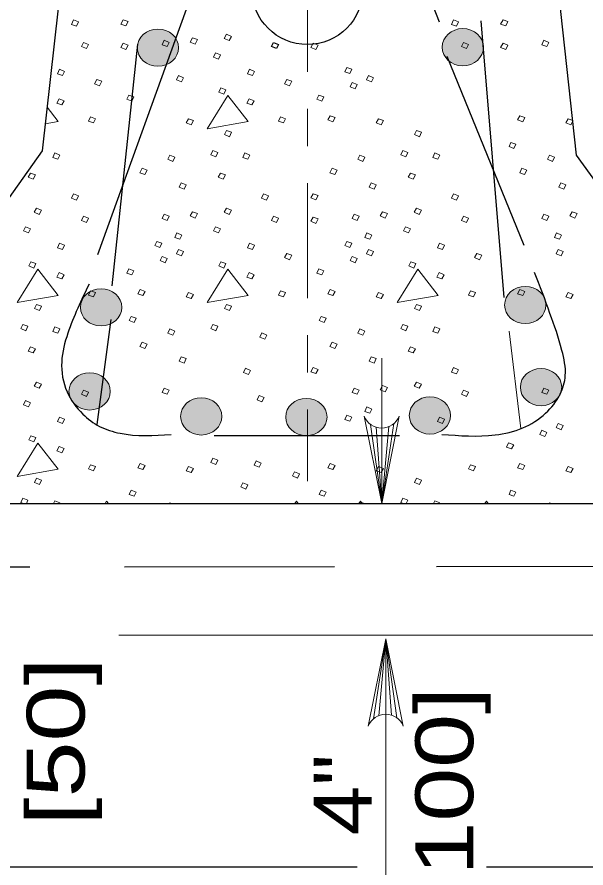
# Model space of a CAD drawing. Extents: x 1083.1 to 1123, y 697.4 to 741.4.
# Drawn here: x 1092.52 to 1094.054, y 703.761 to 706.055 of the extents above; entities that cross this region are included whole.
import ezdxf
from ezdxf.enums import TextEntityAlignment as Align

# ---------------------------------------------------------------- set-up
doc = ezdxf.new("R2010")
doc.units = 0
doc.header["$LTSCALE"] = 0.062
doc.linetypes.add('DOT_DASHED', pattern=[7.7, 5, -1.2, 0.3, -1.2])
doc.layers.add('1', color=7, linetype='Continuous', lineweight=13)

msp = doc.modelspace()

# ---------------------------------------------------------------- hatches: boundary and pattern name
at = {"layer": '1'}
h = msp.add_hatch(color=256, dxfattribs=at)
edge = h.paths.add_edge_path()
edge.add_ellipse((1092.89979, 705.97227), major_axis=(0.05572, 0), ratio=0.8999053, start_angle=0, end_angle=360)
h = msp.add_hatch(color=256, dxfattribs=at)
edge = h.paths.add_edge_path()
edge.add_ellipse((1093.72164, 705.97356), major_axis=(0.05572, 0), ratio=0.8999053, start_angle=0, end_angle=360)
h = msp.add_hatch(color=256, dxfattribs=at)
edge = h.paths.add_edge_path()
edge.add_ellipse((1093.89001, 705.27866), major_axis=(0.05572, 0), ratio=0.8999053, start_angle=0, end_angle=360)
h = msp.add_hatch(color=256, dxfattribs=at)
edge = h.paths.add_edge_path()
edge.add_ellipse((1092.74659, 705.27236), major_axis=(0.05572, 0), ratio=0.8999053, start_angle=0, end_angle=360)
h = msp.add_hatch(color=256, dxfattribs=at)
edge = h.paths.add_edge_path()
edge.add_ellipse((1093.93249, 705.05724), major_axis=(0.05572, 0), ratio=0.8999053, start_angle=0, end_angle=360)
h = msp.add_hatch(color=256, dxfattribs=at)
edge = h.paths.add_edge_path()
edge.add_ellipse((1092.7157, 705.04577), major_axis=(0.05572, 0), ratio=0.8999053, start_angle=0, end_angle=360)
h = msp.add_hatch(color=256, dxfattribs=at)
edge = h.paths.add_edge_path()
edge.add_ellipse((1093.63301, 704.98095), major_axis=(0.05572, 0), ratio=0.8999053, start_angle=0, end_angle=360)
h = msp.add_hatch(color=256, dxfattribs=at)
edge = h.paths.add_edge_path()
edge.add_ellipse((1093.01662, 704.97837), major_axis=(0.05572, 0), ratio=0.8999053, start_angle=0, end_angle=360)
h = msp.add_hatch(color=256, dxfattribs=at)
edge = h.paths.add_edge_path()
edge.add_ellipse((1093.29994, 704.97667), major_axis=(0.05572, 0), ratio=0.8999053, start_angle=0, end_angle=360)

# ---------------------------------------------------------------- linework, layer by layer
at = {"layer": '1', "linetype": 'DOT_DASHED'}
msp.add_line((1093.30267, 707.43708), (1093.30267, 704.80367), dxfattribs=at)
at = {"layer": '1', "lineweight": 25}
for p, q in [((1093.16208, 706.59233), (1092.73708, 705.41425)), ((1093.65925, 706.04117), (1093.43958, 706.5975)), ((1093.83275, 705.299), (1093.77133, 706.04458)), ((1092.84492, 705.98158), (1092.77592, 705.33008)), ((1093.88683, 705.439), (1093.67975, 705.94892)), ((1092.77292, 705.23925), (1092.735, 704.95617)), ((1093.05133, 704.92658), (1093.55092, 704.92658)), ((1092.1595, 704.74317), (1094.45958, 704.74317)), ((1092.55433, 704.57217), (1092.09758, 704.57167)), ((1093.37617, 704.573), (1092.80958, 704.57242)), ((1094.23692, 704.57392), (1093.65075, 704.57333)), ((1092.13858, 703.76442), (1093.4365, 703.76442)), ((1093.78567, 703.76442), (1094.45983, 703.76442))]:
    msp.add_line(p, q, dxfattribs=at)
at = {"layer": '1'}
for p, q in [((1094.006, 705.78067), (1094.01808, 705.77625)), ((1093.84683, 705.20783), (1093.87842, 704.94542)), ((1093.50292, 705.13492), (1093.50292, 704.74317)), ((1093.47308, 704.95642), (1093.50292, 704.74317)), ((1093.48783, 704.94925), (1093.50292, 704.74317)), ((1093.53592, 704.959), (1093.50292, 704.74317)), ((1093.52208, 704.95083), (1093.50292, 704.74317)), ((1093.50292, 704.947), (1093.50292, 704.74317)), ((1092.61867, 704.74317), (1092.62217, 704.75108)), ((1092.76133, 704.7495), (1092.75742, 704.74317)), ((1092.76633, 704.74317), (1092.76133, 704.7495)), ((1092.93092, 704.74317), (1092.932, 704.74542)), ((1092.932, 704.74542), (1092.93733, 704.74317)), ((1093.27325, 704.7495), (1093.26925, 704.74317)), ((1093.27817, 704.74317), (1093.27325, 704.7495)), ((1093.44575, 704.7495), (1093.44175, 704.74317)), ((1093.44275, 704.74317), (1093.44383, 704.74542)), ((1093.44383, 704.74542), (1093.44925, 704.74317)), ((1093.45067, 704.74317), (1093.44575, 704.7495)), ((1093.44983, 704.74317), (1093.45092, 704.74542)), ((1093.45092, 704.74542), (1093.45633, 704.74317)), ((1093.64242, 704.74317), (1093.64592, 704.75108)), ((1093.78508, 704.7495), (1093.78117, 704.74317)), ((1093.79, 704.74317), (1093.78508, 704.7495)), ((1093.95458, 704.74317), (1093.95567, 704.74542)), ((1093.95567, 704.74542), (1093.96108, 704.74317)), ((1092.79442, 704.3885), (1094.97683, 704.3885)), ((1093.481, 704.16333), (1093.514, 704.37917)), ((1093.49483, 704.1715), (1093.514, 704.37917)), ((1093.514, 704.37917), (1093.514, 703.5205)), ((1093.514, 704.17533), (1093.514, 704.37917)), ((1093.52908, 704.17308), (1093.514, 704.37917)), ((1093.54383, 704.16592), (1093.514, 704.37917))]:
    msp.add_line(p, q, dxfattribs=at)
at = {"layer": '1', "lineweight": 25}
for points in [[(1092.759, 707.22517), (1092.58783, 705.69442), (1092.046, 704.92958)], [(1094.57242, 704.93058), (1094.02833, 705.68267), (1093.86025, 707.22475)]]:
    msp.add_lwpolyline(points, dxfattribs=at)
at = {"layer": '1'}
for points in [[(1092.67242, 706.04733), (1092.68592, 706.04167), (1092.68058, 706.03033), (1092.66708, 706.03517)], [(1092.80625, 706.04733), (1092.81975, 706.04242), (1092.81342, 706.03117), (1092.8, 706.036)], [(1093.69617, 706.04733), (1093.70967, 706.04167), (1093.70425, 706.03033), (1093.69075, 706.03517)], [(1093.83, 706.04733), (1093.84342, 706.04242), (1093.83717, 706.03117), (1093.82367, 706.036)], [(1092.99308, 705.99883), (1093.0065, 705.994), (1093.00025, 705.98183), (1092.98675, 705.9875)], [(1093.08467, 706.0085), (1093.09808, 706.00283), (1093.09183, 705.9915), (1093.07833, 705.99717)], [(1092.69942, 705.98667), (1092.71283, 705.981), (1092.7075, 705.96975), (1092.694, 705.97542)], [(1092.80625, 705.98425), (1092.81975, 705.97942), (1092.81342, 705.96733), (1092.8, 705.97292)], [(1092.91675, 705.99233), (1092.93017, 705.98667), (1092.92483, 705.97542), (1092.91133, 705.98025)], [(1093.31808, 705.98425), (1093.33158, 705.97942), (1093.32533, 705.96733), (1093.31183, 705.97292)], [(1093.72308, 705.98667), (1093.73658, 705.981), (1093.73125, 705.96975), (1093.71775, 705.97542)], [(1093.83, 705.98425), (1093.84342, 705.97942), (1093.83717, 705.96733), (1093.82367, 705.97292)], [(1093.94042, 705.99233), (1093.95392, 705.98667), (1093.9485, 705.97542), (1093.93508, 705.98025)], [(1093.055, 705.95842), (1093.0685, 705.95275), (1093.06308, 705.94142), (1093.04958, 705.94708)], [(1092.63475, 705.914), (1092.64825, 705.90833), (1092.64283, 705.897), (1092.62933, 705.90183)], [(1093.14658, 705.914), (1093.16008, 705.90833), (1093.15467, 705.897), (1093.14125, 705.90183)], [(1093.40883, 705.91883), (1093.42233, 705.914), (1093.41692, 705.90267), (1093.40342, 705.9075)], [(1092.73533, 705.8865), (1092.74875, 705.88167), (1092.7425, 705.8695), (1092.729, 705.87517)], [(1092.95533, 705.897), (1092.96883, 705.89133), (1092.96342, 705.88), (1092.94992, 705.88567)], [(1093.24717, 705.8865), (1093.26067, 705.88167), (1093.25433, 705.8695), (1093.24092, 705.87517)], [(1093.46717, 705.897), (1093.48067, 705.89133), (1093.47525, 705.88), (1093.46183, 705.88567)], [(1093.06933, 705.86383), (1093.08283, 705.859), (1093.0775, 705.84692), (1093.064, 705.85258)], [(1093.42317, 705.87842), (1093.43667, 705.87275), (1093.43125, 705.86142), (1093.41783, 705.86708)], [(1092.63383, 705.83475), (1092.64733, 705.82908), (1092.641, 705.81783), (1092.62758, 705.82267)], [(1092.8215, 705.8445), (1092.835, 705.83958), (1092.82958, 705.82833), (1092.81617, 705.83317)], [(1093.08825, 705.84367), (1093.03258, 705.75392), (1093.143, 705.77333)], [(1093.14567, 705.83475), (1093.15917, 705.82908), (1093.15292, 705.81783), (1093.13942, 705.82267)], [(1093.33342, 705.8445), (1093.34683, 705.83958), (1093.3415, 705.82833), (1093.328, 705.83317)], [(1093.36392, 705.78867), (1093.37742, 705.78383), (1093.37108, 705.77258), (1093.35767, 705.77742)], [(1093.87575, 705.78867), (1093.88925, 705.78383), (1093.883, 705.77258), (1093.8695, 705.77742)], [(1092.71825, 705.7855), (1092.73175, 705.78067), (1092.72633, 705.76933), (1092.71283, 705.77417)], [(1092.98225, 705.78067), (1092.99575, 705.77575), (1092.98942, 705.7645), (1092.976, 705.76933)], [(1093.23008, 705.7855), (1093.24358, 705.78067), (1093.23817, 705.76933), (1093.22475, 705.77417)], [(1093.49417, 705.78067), (1093.50758, 705.77575), (1093.50133, 705.7645), (1093.48783, 705.76933)], [(1093.08467, 705.74908), (1093.09808, 705.74425), (1093.09275, 705.73217), (1093.07925, 705.73783)], [(1093.5965, 705.74908), (1093.61, 705.74425), (1093.60458, 705.73217), (1093.59108, 705.73783)], [(1093.8515, 705.71675), (1093.865, 705.71192), (1093.85958, 705.70067), (1093.84617, 705.7055)], [(1092.62217, 705.6885), (1092.63567, 705.68283), (1092.63025, 705.6715), (1092.61675, 705.67633)], [(1092.932, 705.68283), (1092.94542, 705.67717), (1092.94008, 705.66583), (1092.92658, 705.6715)], [(1093.04783, 705.695), (1093.06133, 705.69008), (1093.05592, 705.678), (1093.04242, 705.68367)], [(1093.134, 705.6885), (1093.1475, 705.68283), (1093.14208, 705.6715), (1093.12867, 705.67633)], [(1093.44383, 705.68283), (1093.45733, 705.67717), (1093.45192, 705.66583), (1093.43842, 705.6715)], [(1093.55967, 705.695), (1093.57317, 705.69008), (1093.56775, 705.678), (1093.55433, 705.68367)], [(1093.64592, 705.6885), (1093.65933, 705.68283), (1093.654, 705.6715), (1093.6405, 705.67633)], [(1093.95567, 705.68283), (1093.96917, 705.67717), (1093.96375, 705.66583), (1093.95033, 705.6715)], [(1092.55658, 705.63433), (1092.57008, 705.6295), (1092.56383, 705.61817), (1092.55033, 705.623)], [(1092.85742, 705.64725), (1092.87092, 705.64167), (1092.86467, 705.63033), (1092.85117, 705.63517)], [(1093.0685, 705.63433), (1093.08192, 705.6295), (1093.07567, 705.61817), (1093.06217, 705.623)], [(1093.36933, 705.64725), (1093.38275, 705.64167), (1093.3765, 705.63033), (1093.363, 705.63517)], [(1093.58033, 705.63433), (1093.59383, 705.6295), (1093.5875, 705.61817), (1093.57408, 705.623)], [(1093.88117, 705.64725), (1093.89467, 705.64167), (1093.88833, 705.63033), (1093.87492, 705.63517)], [(1092.9625, 705.60767), (1092.976, 705.60283), (1092.97058, 705.59075), (1092.95717, 705.59633)], [(1093.47442, 705.60767), (1093.48783, 705.60283), (1093.48242, 705.59075), (1093.469, 705.59633)], [(1093.98625, 705.60767), (1093.99967, 705.60283), (1093.99433, 705.59075), (1093.98083, 705.59633)], [(1092.67242, 705.57858), (1092.68592, 705.57292), (1092.68058, 705.56158), (1092.66708, 705.5665)], [(1093.18433, 705.57858), (1093.19775, 705.57292), (1093.19242, 705.56158), (1093.17892, 705.5665)], [(1093.31808, 705.57858), (1093.33158, 705.57375), (1093.32533, 705.56242), (1093.31183, 705.56725)], [(1093.69617, 705.57858), (1093.70967, 705.57292), (1093.70425, 705.56158), (1093.69075, 705.5665)], [(1092.57275, 705.53983), (1092.58625, 705.53417), (1092.57992, 705.52283), (1092.5665, 705.5285)], [(1093.08467, 705.53983), (1093.09808, 705.53417), (1093.09183, 705.52283), (1093.07833, 705.5285)], [(1093.5965, 705.53983), (1093.61, 705.53417), (1093.60367, 705.52283), (1093.59025, 705.5285)], [(1092.69942, 705.518), (1092.71283, 705.51233), (1092.7075, 705.501), (1092.694, 705.50667)], [(1092.91675, 705.52367), (1092.93017, 705.518), (1092.92483, 705.50667), (1092.91133, 705.5115)], [(1092.99308, 705.53008), (1093.0065, 705.52525), (1093.00025, 705.51317), (1092.98675, 705.51883)], [(1093.21125, 705.518), (1093.22475, 705.51233), (1093.21933, 705.501), (1093.20583, 705.50667)], [(1093.31808, 705.51558), (1093.33158, 705.51075), (1093.32533, 705.49858), (1093.31183, 705.50425)], [(1093.42858, 705.52367), (1093.44208, 705.518), (1093.43667, 705.50667), (1093.42317, 705.5115)], [(1093.50492, 705.53008), (1093.51842, 705.52525), (1093.51208, 705.51317), (1093.49858, 705.51883)], [(1093.72308, 705.518), (1093.73658, 705.51233), (1093.73125, 705.501), (1093.71775, 705.50667)], [(1093.94042, 705.52367), (1093.95392, 705.518), (1093.9485, 705.50667), (1093.93508, 705.5115)], [(1094.01675, 705.53008), (1094.03025, 705.52525), (1094.02392, 705.51317), (1094.0105, 705.51883)], [(1092.54317, 705.48967), (1092.55658, 705.48408), (1092.55125, 705.47275), (1092.53775, 705.47842)], [(1093.055, 705.48967), (1093.0685, 705.48408), (1093.06308, 705.47275), (1093.04958, 705.47842)], [(1093.56683, 705.48967), (1093.58033, 705.48408), (1093.57492, 705.47275), (1093.5615, 705.47842)], [(1092.95083, 705.47275), (1092.96433, 705.46708), (1092.95892, 705.45575), (1092.94542, 705.46058)], [(1093.46267, 705.47275), (1093.47617, 705.46708), (1093.47075, 705.45575), (1093.45733, 705.46058)], [(1093.97458, 705.47275), (1093.988, 705.46708), (1093.98267, 705.45575), (1093.96917, 705.46058)], [(1092.63475, 705.44525), (1092.64825, 705.43958), (1092.64283, 705.42833), (1092.62933, 705.43317)], [(1092.89692, 705.45008), (1092.91042, 705.44525), (1092.905, 705.43392), (1092.89158, 705.43883)], [(1093.14658, 705.44525), (1093.16008, 705.43958), (1093.15467, 705.42833), (1093.14125, 705.43317)], [(1093.40883, 705.45008), (1093.42233, 705.44525), (1093.41692, 705.43392), (1093.40342, 705.43883)], [(1093.6585, 705.44525), (1093.67192, 705.43958), (1093.66658, 705.42833), (1093.65308, 705.43317)], [(1092.95533, 705.42833), (1092.96883, 705.42267), (1092.96342, 705.41133), (1092.94992, 705.417)], [(1093.46717, 705.42833), (1093.48067, 705.42267), (1093.47525, 705.41133), (1093.46183, 705.417)], [(1093.97908, 705.42833), (1093.9925, 705.42267), (1093.98717, 705.41133), (1093.97367, 705.417)], [(1092.91133, 705.40967), (1092.92483, 705.404), (1092.91942, 705.39275), (1092.90592, 705.39842)], [(1093.24717, 705.41775), (1093.26067, 705.41292), (1093.25433, 705.40083), (1093.24092, 705.4065)], [(1093.42317, 705.40967), (1093.43667, 705.404), (1093.43125, 705.39275), (1093.41783, 705.39842)], [(1093.759, 705.41775), (1093.7725, 705.41292), (1093.76625, 705.40083), (1093.75275, 705.4065)], [(1092.57633, 705.37492), (1092.52067, 705.28525), (1092.63117, 705.30467)], [(1092.5575, 705.39517), (1092.571, 705.39033), (1092.56558, 705.37817), (1092.55217, 705.38383)], [(1092.8215, 705.37575), (1092.835, 705.37092), (1092.82958, 705.35958), (1092.81617, 705.36442)], [(1093.08825, 705.37492), (1093.03258, 705.28525), (1093.143, 705.30467)], [(1093.06933, 705.39517), (1093.08283, 705.39033), (1093.0775, 705.37817), (1093.064, 705.38383)], [(1093.33342, 705.37575), (1093.34683, 705.37092), (1093.3415, 705.35958), (1093.328, 705.36442)], [(1093.60008, 705.37492), (1093.54442, 705.28525), (1093.65492, 705.30467)], [(1093.58125, 705.39517), (1093.59467, 705.39033), (1093.58933, 705.37817), (1093.57583, 705.38383)], [(1092.63383, 705.36608), (1092.64733, 705.36042), (1092.641, 705.34908), (1092.62758, 705.35392)], [(1093.14567, 705.36608), (1093.15917, 705.36042), (1093.15292, 705.34908), (1093.13942, 705.35392)], [(1093.65758, 705.36608), (1093.671, 705.36042), (1093.66475, 705.34908), (1093.65125, 705.35392)], [(1092.71825, 705.31675), (1092.73175, 705.31192), (1092.72633, 705.30058), (1092.71283, 705.30542)], [(1092.85208, 705.32), (1092.8655, 705.31517), (1092.85925, 705.30383), (1092.84575, 705.30867)], [(1092.98225, 705.31192), (1092.99575, 705.30708), (1092.98942, 705.29575), (1092.976, 705.30058)], [(1093.23008, 705.31675), (1093.24358, 705.31192), (1093.23817, 705.30058), (1093.22475, 705.30542)], [(1093.36392, 705.32), (1093.37742, 705.31517), (1093.37108, 705.30383), (1093.35767, 705.30867)], [(1093.49417, 705.31192), (1093.50758, 705.30708), (1093.50133, 705.29575), (1093.48783, 705.30058)], [(1093.742, 705.31675), (1093.75542, 705.31192), (1093.75008, 705.30058), (1093.73658, 705.30542)], [(1093.87575, 705.32), (1093.88925, 705.31517), (1093.883, 705.30383), (1093.8695, 705.30867)], [(1094.006, 705.31192), (1094.0195, 705.30708), (1094.01317, 705.29575), (1093.99967, 705.30058)], [(1092.57275, 705.28042), (1092.58625, 705.27558), (1092.58083, 705.26342), (1092.56742, 705.26908)], [(1093.08467, 705.28042), (1093.09808, 705.27558), (1093.09275, 705.26342), (1093.07925, 705.26908)], [(1093.5965, 705.28042), (1093.61, 705.27558), (1093.60458, 705.26342), (1093.59108, 705.26908)], [(1092.82783, 705.24808), (1092.84125, 705.24325), (1092.83592, 705.23192), (1092.82242, 705.23675)], [(1093.33967, 705.24808), (1093.35317, 705.24325), (1093.34775, 705.23192), (1093.33425, 705.23675)], [(1092.536, 705.22625), (1092.54942, 705.22142), (1092.54408, 705.20933), (1092.53058, 705.21492)], [(1092.62217, 705.21983), (1092.63567, 705.21417), (1092.63025, 705.20283), (1092.61675, 705.20767)], [(1092.932, 705.21417), (1092.94542, 705.2085), (1092.94008, 705.19717), (1092.92658, 705.20283)], [(1093.04783, 705.22625), (1093.06133, 705.22142), (1093.05592, 705.20933), (1093.04242, 705.21492)], [(1093.44383, 705.21417), (1093.45733, 705.2085), (1093.45192, 705.19717), (1093.43842, 705.20283)], [(1093.55967, 705.22625), (1093.57317, 705.22142), (1093.56775, 705.20933), (1093.55433, 705.21492)], [(1093.64592, 705.21983), (1093.65933, 705.21417), (1093.654, 705.20283), (1093.6405, 705.20767)], [(1093.17958, 705.20342), (1093.19308, 705.19775), (1093.18767, 705.18642), (1093.17425, 705.19208)], [(1092.85742, 705.17858), (1092.87092, 705.17292), (1092.86467, 705.16158), (1092.85117, 705.16642)], [(1093.36933, 705.17858), (1093.38275, 705.17292), (1093.3765, 705.16158), (1093.363, 705.16642)], [(1092.55658, 705.16567), (1092.57008, 705.16083), (1092.56383, 705.1495), (1092.55033, 705.15433)], [(1093.58033, 705.16567), (1093.59383, 705.16083), (1093.5875, 705.1495), (1093.57408, 705.15433)], [(1092.9625, 705.139), (1092.976, 705.13417), (1092.97058, 705.122), (1092.95717, 705.12767)], [(1093.47442, 705.139), (1093.48783, 705.13417), (1093.48242, 705.122), (1093.469, 705.12767)], [(1093.13567, 705.108), (1093.14908, 705.10233), (1093.14375, 705.091), (1093.13025, 705.09667)], [(1093.31808, 705.10992), (1093.33158, 705.10508), (1093.32533, 705.09375), (1093.31183, 705.09858)], [(1093.69617, 705.10992), (1093.70967, 705.10425), (1093.70425, 705.09292), (1093.69075, 705.09775)], [(1092.57275, 705.07108), (1092.58625, 705.06542), (1092.57992, 705.05417), (1092.5665, 705.05975)], [(1092.91675, 705.05492), (1092.93017, 705.04925), (1092.92483, 705.038), (1092.91133, 705.04283)], [(1093.42858, 705.05492), (1093.44208, 705.04925), (1093.43667, 705.038), (1093.42317, 705.04283)], [(1093.50492, 705.06142), (1093.51842, 705.05658), (1093.51208, 705.04442), (1093.49858, 705.05008)], [(1093.5965, 705.07108), (1093.61, 705.06542), (1093.60367, 705.05417), (1093.59025, 705.05975)], [(1093.94042, 705.05492), (1093.95392, 705.04925), (1093.9485, 705.038), (1093.93508, 705.04283)], [(1092.69942, 705.04925), (1092.71283, 705.04367), (1092.7075, 705.03233), (1092.694, 705.038)], [(1093.17225, 705.03458), (1093.18575, 705.02892), (1093.18033, 705.01758), (1093.16692, 705.02325)], [(1093.72308, 705.04925), (1093.73658, 705.04367), (1093.73125, 705.03233), (1093.71775, 705.038)], [(1092.54317, 705.021), (1092.55658, 705.01533), (1092.55125, 705.004), (1092.53775, 705.00967)], [(1093.46267, 705.004), (1093.47617, 704.99833), (1093.47075, 704.98708), (1093.45733, 704.99192)], [(1092.63475, 704.97658), (1092.64825, 704.97092), (1092.64283, 704.95958), (1092.62933, 704.96442)], [(1093.40883, 704.98142), (1093.42233, 704.97658), (1093.41692, 704.96525), (1093.40342, 704.97008)], [(1093.6585, 704.97658), (1093.67192, 704.97092), (1093.66658, 704.95958), (1093.65308, 704.96442)], [(1093.93508, 704.941), (1093.9485, 704.93533), (1093.94317, 704.924), (1093.92967, 704.92967)], [(1093.97908, 704.95958), (1093.9925, 704.95392), (1093.98717, 704.94258), (1093.97367, 704.94825)], [(1092.5575, 704.92642), (1092.571, 704.92158), (1092.56558, 704.9095), (1092.55217, 704.91517)], [(1092.57633, 704.90625), (1092.52067, 704.8165), (1092.63117, 704.83592)], [(1092.63383, 704.89733), (1092.64733, 704.89167), (1092.641, 704.88042), (1092.62758, 704.88525)], [(1093.84525, 704.90708), (1093.85875, 704.90217), (1093.85333, 704.89092), (1093.83983, 704.89575)], [(1092.71825, 704.84808), (1092.73175, 704.84325), (1092.72633, 704.83192), (1092.71283, 704.83675)], [(1092.85208, 704.85125), (1092.8655, 704.84642), (1092.85925, 704.83517), (1092.84575, 704.84)], [(1093.04767, 704.86575), (1093.06117, 704.86008), (1093.05575, 704.84875), (1093.04225, 704.85442)], [(1093.16492, 704.85842), (1093.17842, 704.85275), (1093.173, 704.84142), (1093.15958, 704.84708)], [(1093.36392, 704.85125), (1093.37742, 704.84642), (1093.37108, 704.83517), (1093.35767, 704.84)], [(1093.742, 704.84808), (1093.75542, 704.84325), (1093.75008, 704.83192), (1093.73658, 704.83675)], [(1093.87575, 704.85125), (1093.88925, 704.84642), (1093.883, 704.83517), (1093.8695, 704.84)], [(1092.98225, 704.84325), (1092.99575, 704.83833), (1092.98942, 704.82708), (1092.976, 704.83192)], [(1093.26758, 704.829), (1093.281, 704.82333), (1093.27567, 704.81208), (1093.26217, 704.81775)], [(1093.49417, 704.84325), (1093.50758, 704.83833), (1093.50133, 704.82708), (1093.48783, 704.83192)], [(1094.006, 704.84325), (1094.0195, 704.83833), (1094.01317, 704.82708), (1093.99967, 704.83192)], [(1092.57275, 704.81167), (1092.58625, 704.80683), (1092.58083, 704.79475), (1092.56742, 704.80042)], [(1093.5965, 704.81167), (1093.61, 704.80683), (1093.60458, 704.79475), (1093.59108, 704.80042)], [(1092.82783, 704.77933), (1092.84125, 704.7745), (1092.83592, 704.76325), (1092.82242, 704.76808)], [(1093.12833, 704.79967), (1093.14175, 704.794), (1093.13642, 704.78267), (1093.12292, 704.78833)], [(1093.33967, 704.77933), (1093.35317, 704.7745), (1093.34775, 704.76325), (1093.33425, 704.76808)], [(1093.8515, 704.77933), (1093.865, 704.7745), (1093.85958, 704.76325), (1093.84617, 704.76808)]]:
    msp.add_lwpolyline(points, close=True, dxfattribs=at)
at = {"layer": '1', "lineweight": 25}
msp.add_lwpolyline([(1093.21125, 705.98667), (1093.22475, 705.981), (1093.21933, 705.96975), (1093.20583, 705.97542)], close=True, dxfattribs=at)
at = {"layer": '1'}
for points in [[(1092.596, 705.76717), (1092.63117, 705.77333), (1092.601, 705.81208)], [(1094.01842, 705.77392), (1094.01317, 705.7645), (1093.99967, 705.76933), (1094.006, 705.78067)], [(1093.55008, 704.97875), (1093.50292, 704.74317), (1093.45583, 704.97875)], [(1092.53783, 704.74317), (1092.53058, 704.74625), (1092.536, 704.75758)], [(1092.536, 704.75758), (1092.54942, 704.75267), (1092.54525, 704.74317)], [(1093.56158, 704.74317), (1093.55433, 704.74625), (1093.55967, 704.75758)], [(1093.55967, 704.75758), (1093.57317, 704.75267), (1093.56892, 704.74317)], [(1092.62217, 704.75108), (1092.63567, 704.74542), (1092.63458, 704.74317)], [(1093.64592, 704.75108), (1093.65933, 704.74542), (1093.65825, 704.74317)], [(1093.46683, 704.14358), (1093.514, 704.37917), (1093.56108, 704.14358)]]:
    msp.add_lwpolyline(points, dxfattribs=at)
at = {"layer": '1', "lineweight": 25}
msp.add_circle((1093.30275, 706.13058), 0.14994, dxfattribs=at)
at = {"layer": '1'}
for centre, start, end in [((1093.50289, 704.99777), 202.08782, 337.91395), ((1093.51405, 704.12456), 22.08782, 157.91395)]:
    msp.add_arc(centre, 0.05085, start, end, dxfattribs=at)
for centre in [(1092.89979, 705.97227), (1093.72164, 705.97356), (1093.89001, 705.27866), (1092.74659, 705.27236), (1093.93249, 705.05724), (1092.7157, 705.04577), (1093.63301, 704.98095), (1093.01662, 704.97837), (1093.29994, 704.97667)]:
    msp.add_ellipse(centre, major_axis=(0.05572, 0), ratio=0.899905, dxfattribs=at)
at = {"layer": '1', "lineweight": 25}
for points in [[(1093.665, 704.93), (1093.80908, 704.92858), (1093.88308, 704.94725), (1093.94475, 704.98692), (1093.98417, 705.0385), (1093.998, 705.08842), (1093.98875, 705.15642), (1093.95667, 705.25617), (1093.91517, 705.3665)], [(1092.71408, 705.33525), (1092.65692, 705.20258), (1092.64042, 705.12558), (1092.65475, 705.04492), (1092.69725, 704.98467), (1092.74242, 704.95158), (1092.79758, 704.93292), (1092.93508, 704.9295)]]:
    msp.add_spline(points, degree=3, dxfattribs=at)

# ---------------------------------------------------------------- texts
at = {"layer": '1'}
for s, width, p in [('[50]', 1.3, (1092.70225, 704.10204)), ('[100]', 1.25, (1093.74967, 703.95875)), ('4"', 1.15, (1093.47567, 703.95875))]:
    msp.add_text(s, height=0.156, rotation=90, dxfattribs=dict(at, width=width)).set_placement(p, align=Align.CENTER)

doc.saveas('drawing.dxf')
